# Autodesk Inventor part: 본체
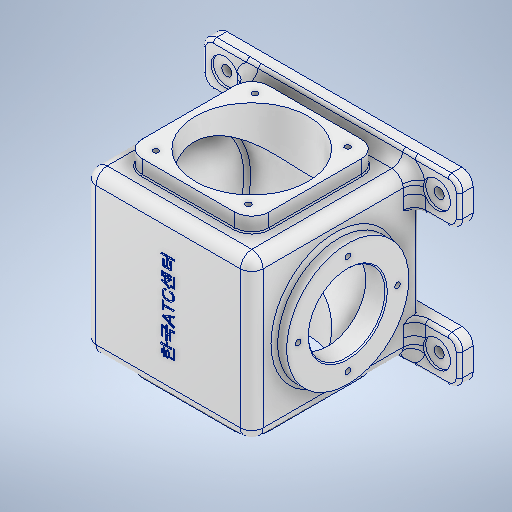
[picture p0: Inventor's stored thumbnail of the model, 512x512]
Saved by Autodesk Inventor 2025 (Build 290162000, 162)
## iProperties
Created: 2026-01
Part Number: 본체
Material: 알루미늄 6061
Document SubType Name: Modeling
Designer: KDI
Density: 2.7 g/cm^3
Appearance: 알루미늄 - 평지
Mass: 3953.42 g
Surface Area: 2287.79 cm^2
Volume: 1464.23 cm^3
Author: KDI
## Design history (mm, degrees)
sketch "스케치2"
  geometry: L1 (114, 81)-(-114, 81); L2 (-114, -81)-(114, -81); L3 (114, 81)-(-114, -81); L4 (-114, 81)-(114, -81); L5 (-114, 41)-(114, 41); L6 (0, 0)-(14.996, 0); L7 (-114, -41)-(114, -41); L8 (-114, 81)-(-114, 41); L9 (-114, -41)-(-114, -81); L10 (114, -81)-(114, -41); L11 (114, 41)-(114, 81)
  constraints: 22 end point, 5 parallel, 4 perpendicular, 2 horizontal, 2 midpoint, 2 symmetric about line
  dimensions: "d0" = 228 distance of L2.end L2.start; "d1" = 162 distance of L2.start L1.end
extrude "돌출1" new body sketch "스케치2" distance "d3" = 12; taper "d4" = 0 deg
node "작업 평면1"
sketch "스케치3"
  geometry: L1 (-74, 71)-(74, 71); L2 (74, 71)-(74, -71); L3 (74, -71)-(-74, -71); L4 (-74, -71)-(-74, 71); L5 (-74, 71)-(74, -71); L6 (74, 71)-(-74, -71); 1 further point
  constraints: 12 end point, 2 midpoint, 2 parallel, 1 horizontal, 1 perpendicular
  dimensions: "d6" = 148 distance of L2.end L3.end; "d7" = 142 distance of L1.end L2.end
extrude "돌출2" join sketch "스케치3" distance "d8" = 148; taper "d9" = 0 deg
fillet "모깎기1" dims "d10" = 10
sketch "스케치7"
  geometry: 5 further points
hole "구멍2" sketch "스케치7" at (-94, -61), (-94, 61), (94, 61), (94, -61) diameter "d38" = 9; stored, may be unused: countersink angle "d42" = 82 deg, drill point angle "d44" = 118 deg; dims "d39" = 12, "d40" = 24, "d41" = 2, "d43" = 15
sketch "스케치8"
  geometry: L1 (23, -8)-(105, -8); L2 (120, -23)-(120, -105); L3 (105, -120)-(23, -120); L4 (8, -105)-(8, -23); L5 (8, -8)-(120, -120); L6 (120, -8)-(8, -120); A1 r 15 centre (23, -23) between (23, -8) and (8, -23); A2 r 15 centre (23, -105) between (8, -105) and (23, -120); A3 r 15 centre (105, -105) between (105, -120) and (120, -105); A4 r 15 centre (105, -23) between (120, -23) and (105, -8); 1 further point
  constraints: 12 end point, 8 point on circle, 8 point on line, 8 tangent, 4 centre point, 3 equal radius, 2 parallel, 1 horizontal, 1 perpendicular
  dimensions: "d46" = 112 distance of L5.end L6.end; "d47" = 112 distance of L6.start L5.end; "d48" = 15 radius of A1 (derived)
extrude "돌출5" join sketch "스케치8" distance "d49" = 13; taper "d50" = 0 deg
sketch "스케치9"
  geometry: L1 (128, -134)-(128, 0) reference; L2 (0, -134)-(128, -134) reference; L3 (0, 0)-(0, -134) reference; L4 (128, 0)-(0, 0) reference; C1 r 50 at (64, -64); 1 further point
  constraints: 1 centre point
  dimensions: "d52" = 100 diameter of C1
extrude "돌출6" cut sketch "스케치9" distance "d53" = 13; taper "d54" = 0 deg
sketch "스케치10"
  geometry: 5 further points
hole "구멍3" sketch "스케치10" at (23, -20), (105, -20), (105, -108), (23, -108) diameter "d58" = 4.917; stored, may be unused: countersink angle "d62" = 90 deg, drill point angle "d64" = 118 deg; dims "d59" = 12, "d60" = 3.6, "d61" = 2, "d63" = 14
chamfer "모따기2" distance "d65" = 1; stored, may be unused: second distance "d66" = 2, angle "d67" = 45 deg
chamfer "모따기3" distance "d68" = 1; stored, may be unused: second distance "d69" = 2, angle "d70" = 45 deg
sketch "스케치11"
  geometry: C1 r 50 at (0, 0); 1 further point
  constraints: 1 centre point
extrude "돌출7" cut sketch "스케치11" extent not by distance; stored distance "d71" = 0; taper "d72" = 0 deg
fillet "모깎기2" dims "d73" = 10
sketch "스케치12"
  geometry: C1 r 54 at (-74, 41); 1 further point
  constraints: 1 centre point
  dimensions: "d76" = 108 diameter of C1
extrude "돌출8" join sketch "스케치12" distance "d77" = 11; taper "d78" = 0 deg
sketch "스케치13"
  geometry: C1 r 34 at (0, 0); 1 further point
  constraints: 1 centre point
  dimensions: "d79" = 68 diameter of C1
extrude "돌출9" cut sketch "스케치13" distance "d80" = 87.5; taper "d81" = 0 deg
sketch "스케치14"
  geometry: 2 further points
hole "구멍4" sketch "스케치14" at (-44, 0) diameter "d83" = 4.917; stored, may be unused: countersink angle "d87" = 90 deg, drill point angle "d89" = 118 deg; dims "d84" = 12, "d85" = 4, "d86" = 2, "d88" = 14
fillet "모깎기4" dims "d93" = 3
sketch "스케치15"
  geometry: 2 further points
  constraints: 2 coincident, 1 other
feature "엠보싱1" sketch "스케치15" dims "d94" = 0.5, "d95" = 0
fillet "모깎기5" dims "d96" = 3
fillet "모깎기6" dims "d97" = 10
fillet "모깎기7" dims "d98" = 3
chamfer "모따기4" distance "d99" = 1; stored, may be unused: second distance "d100" = 2, angle "d101" = 45 deg
sketch "스케치16"
  geometry: L1 (159.6, 8)-(-159.6, 8) reference; L2 (74, 22)-(74, 146) reference; L3 (64, 156)-(-64, 156) reference; L4 (-74, 146)-(-74, 22) reference; L5 (64, 149)-(-64, 149); L6 (67, 84)-(67, 146); L7 (-67, 146)-(-67, 84); L8 (-67, 84)-(74, 84); A1 r 3 centre (64, 146) between (67, 146) and (64, 149); A2 r 3 centre (-64, 146) between (-64, 149) and (-67, 146); 1 further point
  constraints: 8 end point, 4 point on circle, 4 tangent, 3 parallel, 2 centre point, 1 midpoint, 1 point on line
  dimensions: "d102" = 7 distance between parallel lines of L3 L5; "d103" = 7 distance between parallel lines of L2 L6; "d104" = 7 distance between parallel lines of L4 L7
revolve "회전1" sketch "스케치16" stored, may be unused: angle "d106" = 90 deg
node "솔리드1"
mirror "미러2"
mirror "미러3"
pattern_circular "원형 패턴1" dims angle "d91" = 360 deg
node "투영된 루프1"
feature "A9D066F2-1C7D-4E18-AEED-F7BC21143FA4" dims "d38" = 9, "d39" = 12, "d40" = 24, "d41" = 2, "d42" = 82 deg, "d43" = 15, "d44" = 118 deg
other parameters: "d5" = -8
